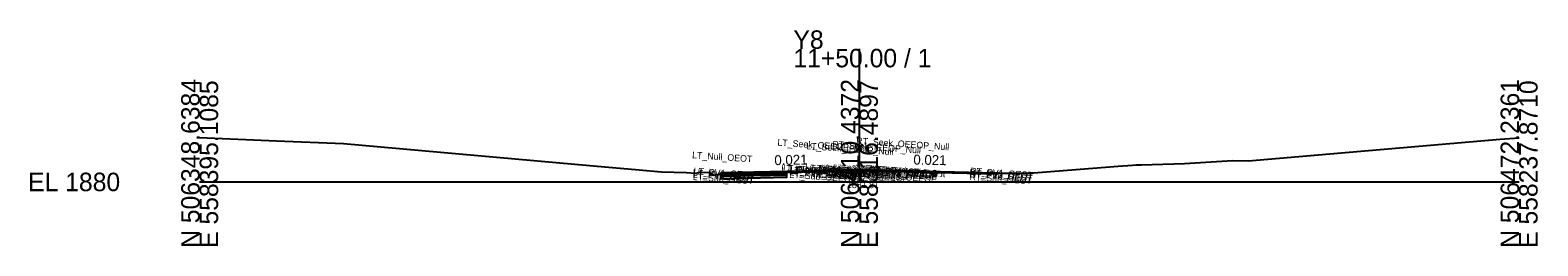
# Model space of a CAD drawing. Extents: x -26 to 203, y -10 to 8070.
# Drawn here: x -25.7 to 202.8, y 1490.3 to 1523 of the extents above; entities that cross this region are included whole.
import ezdxf

# ---------------------------------------------------------------- set-up
doc = ezdxf.new("R2010")
doc.units = 0
for name, color, linetype in [('Default', 7, 'Continuous'), ('Exist Cross Section Cell', 7, 'Continuous'), ('Exist XS Center Line Elevation Label', 7, 'Continuous'), ('Exist XS Ground Line', 7, 'Continuous'), ('Prop CMT Pvmt Course 1', 7, 'Continuous'), ('Prop CMT Pvmt Course 2', 7, 'Continuous'), ('Prop CMT Pvmt Course 3', 7, 'Continuous'), ('Prop CMT Pvmt Surface', 7, 'Continuous'), ('Prop CMT Subgrade Earthwork', 7, 'Continuous'), ('Prop XS Earthwork Shape', 7, 'Continuous'), ('Prop XS SE Text', 7, 'Continuous'), ('Typical Text Grade Point CELL', 7, 'Continuous')]:
    doc.layers.add(name, color=color, linetype=linetype)

msp = doc.modelspace()

# ---------------------------------------------------------------- linework, layer by layer
at = {"layer": 'Exist Cross Section Cell'}
for p, q in [((100, 1500), (100, 1520.18)), ((0, 1500), (100, 1500)), ((100, 1500), (200, 1500))]:
    msp.add_line(p, q, dxfattribs=at)
at = {"layer": 'Exist XS Ground Line'}
for p, q in [((0, 1506.73), (11.63, 1506.24)), ((11.63, 1506.24), (21.82, 1505.84)), ((158.99, 1503.21), (197.13, 1506.48)), ((197.13, 1506.48), (200, 1506.69)), ((21.82, 1505.84), (59.7, 1502.44)), ((59.7, 1502.44), (66.64, 1501.82)), ((66.64, 1501.82), (69.98, 1501.54)), ((69.98, 1501.54), (73.78, 1501.42)), ((75.71, 1501.44), (77.22, 1501.46)), ((77.22, 1501.46), (77.9, 1501.03)), ((81.31, 1501.29), (87.11, 1501.55)), ((87.11, 1501.55), (96.89, 1501.76)), ((96.89, 1501.76), (100, 1501.81)), ((100, 1501.81), (100.74, 1501.82)), ((100.74, 1501.82), (106.08, 1501.71)), ((106.08, 1501.71), (120.75, 1501.35)), ((125.78, 1501.33), (139.21, 1502.37)), ((139.21, 1502.37), (141.42, 1502.55)), ((141.42, 1502.55), (141.97, 1502.58)), ((141.97, 1502.58), (142.74, 1502.59)), ((142.74, 1502.59), (149.29, 1502.81)), ((149.29, 1502.81), (156.56, 1503.23)), ((156.56, 1503.23), (158.99, 1503.21)), ((73.78, 1501.42), (75.16, 1501.35)), ((75.16, 1501.35), (75.71, 1501.44)), ((77.9, 1501.03), (78.82, 1501.2)), ((78.82, 1501.2), (79.17, 1501.22)), ((79.17, 1501.22), (81.31, 1501.29)), ((120.75, 1501.35), (124.33, 1501.34)), ((124.33, 1501.34), (125.78, 1501.33))]:
    msp.add_line(p, q, dxfattribs=at)
at = {"layer": 'Prop CMT Pvmt Course 1'}
for points in [[(100, 1501.81), (98, 1501.78), (97.99, 1501.78), (94.01, 1501.7), (94, 1501.7), (79, 1501.37)], [(100, 1501.81), (102, 1501.79), (102.01, 1501.79), (105.99, 1501.7), (106, 1501.7), (121, 1501.37)], [(79, 1501.37), (79, 1501.12)], [(79, 1501.12), (89, 1501.33)]]:
    msp.add_lwpolyline(points, dxfattribs=at)
at = {"layer": 'Prop CMT Pvmt Course 2'}
for points in [[(89, 1501.33), (79, 1501.12)], [(79, 1501.12), (79, 1500.87)], [(79, 1500.87), (89, 1501.08)]]:
    msp.add_lwpolyline(points, dxfattribs=at)
at = {"layer": 'Prop CMT Pvmt Course 3'}
for points in [[(89, 1501.08), (79, 1500.87)], [(79, 1500.87), (79, 1500.49)], [(79, 1500.49), (89, 1500.7)]]:
    msp.add_lwpolyline(points, dxfattribs=at)
at = {"layer": 'Prop CMT Pvmt Surface'}
for points in [[(100, 1501.81), (98, 1501.78), (97.99, 1501.78), (94.01, 1501.7), (94, 1501.7), (79, 1501.37)], [(100, 1501.81), (102, 1501.79), (102.01, 1501.79), (105.99, 1501.7), (106, 1501.7), (121, 1501.37)]]:
    msp.add_lwpolyline(points, dxfattribs=at)
at = {"layer": 'Prop CMT Subgrade Earthwork'}
for p, q in [((89, 1500.7), (89, 1501.59)), ((79, 1500.49), (79, 1501.21))]:
    msp.add_line(p, q, dxfattribs=at)
msp.add_lwpolyline([(89, 1500.7), (79, 1500.49)], dxfattribs=at)
at = {"layer": 'Prop XS Earthwork Shape'}
for points in [[(121, 1501.25), (121, 1501.37), (120.75, 1501.35), (105.99, 1501.7), (102, 1501.79), (100, 1501.81), (98, 1501.78), (94.01, 1501.7), (87.11, 1501.55), (81.31, 1501.29), (79.17, 1501.22), (79, 1501.21), (79, 1500.49), (89, 1500.7), (89, 1501.45), (100, 1501.68)], [(96.89, 1501.76), (100, 1501.81), (98, 1501.78), (94.01, 1501.7)], [(100.74, 1501.82), (102, 1501.79), (100, 1501.81)]]:
    msp.add_lwpolyline(points, close=True, dxfattribs=at)

# ---------------------------------------------------------------- texts
at = {"layer": 'Default'}
msp.add_text('-', height=0.0001, dxfattribs=at).set_placement((0, 1500))
at = {"layer": 'Exist Cross Section Cell'}
for s, p in [('Y8', (90, 1520.18)), ('11+50.00 / 1', (90, 1517.38)), ('EL 1880', (-26, 1498.6))]:
    msp.add_text(s, height=2.8, dxfattribs=at).set_placement(p)
for s, p in [('N 506348.6384', (0, 1490)), ('E 558395.1085', (2.8, 1490)), ('N 506410.4372', (100, 1490)), ('E 558316.4897', (102.8, 1490)), ('N 506472.2361', (200, 1490)), ('E 558237.8710', (202.8, 1490))]:
    msp.add_text(s, height=2.8, rotation=90, dxfattribs=at).set_placement(p)
at = {"layer": 'Exist XS Center Line Elevation Label'}
msp.add_text('1881.81', height=1, dxfattribs=at).set_placement((98.12, 1499.06))
at = {"layer": 'Prop XS SE Text'}
for rotation, p in [(1.2047, (87.13, 1502.54)), (358.8103, (108.17, 1502.64))]:
    msp.add_text('0.021', height=1.5, rotation=rotation, dxfattribs=at).set_placement(p)
at = {"layer": 'Typical Text Grade Point CELL'}
for s, p in [('LT_Seek_OEEOP_Null', (87.55, 1505.51)), ('RT_Seek_IEEOP_Null', (95.87, 1505.24)), ('RT_Seek_OEEOP_Null', (99.49, 1505.76)), ('LT_Null_OEOT', (74.62, 1503.61)), ('LT_Seek_IEEOP_Null', (91.93, 1504.98)), ('LT_PV2_OEOT', (74.72, 1500.92)), ('LT_PV3_OEOT', (74.72, 1500.67)), ('LT_PV1_OEOT', (74.84, 1501.16)), ('LT_PV_Sub_Tie_Out', (88.14, 1501.61)), ('LT_Null OEEOP Test', (88.4, 1501.64)), ('LT_PV2_OEEOP', (89.37, 1501.26)), ('LT_PV3_OEEOP', (89.37, 1501.01)), ('LT_Sub_OEEOP', (89.39, 1500.63)), ('LT_PV1_OEEOP', (89.49, 1501.37)), ('LT_Pvmt Out', (90.25, 1501.46)), ('LT_Null IEEOP Test', (91.78, 1501.67)), ('LT_PV_Sub_Tie_In', (92.76, 1501.64)), ('LT_PV2_IEEOP', (93.75, 1501.31)), ('LT_PV3_IEEOP', (93.75, 1501.06)), ('LT_Sub_IEEOP', (93.77, 1500.69)), ('LT_PV1_IEEOP', (93.87, 1501.43)), ('Null RT Pvmt Slope', (94.26, 1501.74)), ('Null LT Pvmt Slope', (94.32, 1501.71)), ('PV1_Overlay_Null', (94.75, 1501.55)), ('LT_Pvmt In', (94.84, 1501.5)), ('RT_PV_Sub_Tie_In', (96.7, 1501.66)), ('RT_Null IEEOP Test', (96.72, 1501.68)), ('Sub_PGL', (97.35, 1500.62)), ('PV2_PGL', (97.32, 1501.25)), ('PV3_PGL', (97.32, 1501)), ('PV1_PGL', (97.44, 1501.49)), ('RT_PV2_IEEOP', (97.69, 1501.32)), ('RT_PV3_IEEOP', (97.69, 1501.07)), ('RT_Sub_IEEOP', (97.71, 1500.69)), ('RT_PV1_IEEOP', (97.81, 1501.43)), ('RT_Pvmt In', (98.8, 1501.52)), ('CL', (99.2, 1501.36)), ('RT_Null OEEOP Test', (99.34, 1501.64)), ('RT_PV_Sub_Tie_Out', (100.09, 1501.62)), ('RT_PV2_OEEOP', (101.31, 1501.26)), ('RT_PV3_OEEOP', (101.31, 1501.01)), ('RT_Sub_OEEOP', (101.33, 1500.63)), ('RT_PV1_OEEOP', (101.43, 1501.38)), ('RT_Pvmt Out', (102.17, 1501.47)), ('RT_PV2_OEOT', (116.66, 1500.93)), ('RT_PV3_OEOT', (116.66, 1500.68)), ('RT_PV1_OEOT', (116.78, 1501.17)), ('LT_Sub_OEOT', (74.74, 1500.29)), ('RT_Sub_OEOT', (116.69, 1500.3))]:
    msp.add_text(s, height=1, rotation=356, dxfattribs=at).set_placement(p)

doc.saveas('drawing.dxf')
